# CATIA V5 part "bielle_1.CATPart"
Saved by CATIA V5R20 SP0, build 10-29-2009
Part number: bielle_2
Publications: "bielle2_barre", "bielle2_pivotsup", "bielle2_pivotinf"
Bounding box of the stored display mesh (mm): x -10 to 10, y 350 to 350, z -50 to 0
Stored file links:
  C:\Users\Noëllie\Documents\IFMA\2A\S3\IAO\Projet Artobolevski\Catia\bielle_1.CATPart
  C:\Users\Noëllie\Documents\IFMA\2A\S3\IAO\Projet Artobolevski\Catia\Artobolevski 782.CATProduct
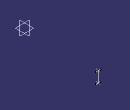
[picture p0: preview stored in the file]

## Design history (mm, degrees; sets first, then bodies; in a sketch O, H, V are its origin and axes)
Set1
  Point1 "B2d": linked copy from another document
  Point2 "C2": linked copy from another document
Body1 (main body)
  Line1 "bielle2_barre": type PtPt, FirstPoint Point1, SecondPoint Point2
  Line2 "bielle2_pivotsup": type PtDir, RefPoint Point1, Direction yz-plane, Start 10, End -10
  Line3 "bielle2_pivotinf": type PtDir, RefPoint Point2, Direction yz-plane, Start 10, End -10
